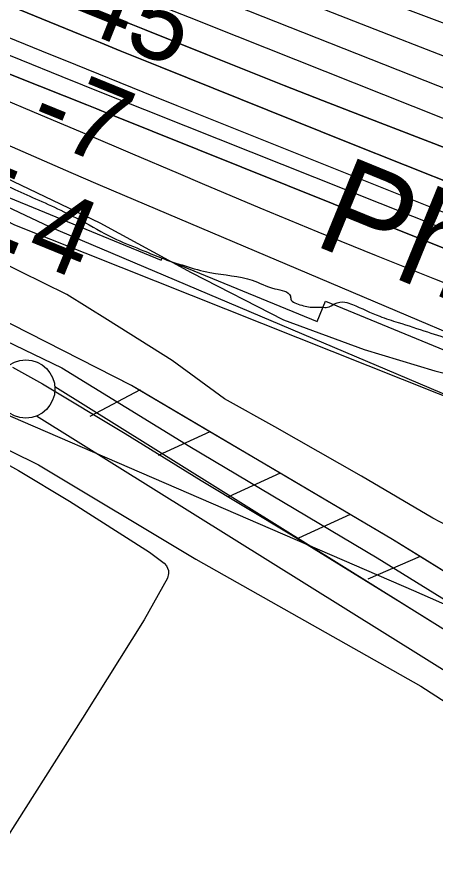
# Model space of a CAD drawing. Extents: x 3734862 to 3772949, y 391520 to 417239.
# Drawn here: x 3741807 to 3742167, y 404825 to 405557 of the extents above; entities that cross this region are included whole.
import ezdxf

# ---------------------------------------------------------------- set-up
doc = ezdxf.new("R2010")
doc.units = 0
for name, color, linetype in [('V-FLOD-BASE', 7, 'Continuous'), ('V-LEVE-TOET', 7, 'Continuous'), ('V-RIVR-EDGE', 7, 'Continuous'), ('V-RIVR-IDEN', 7, 'Continuous'), ('V-RIVR-RANG', 7, 'Continuous'), ('V-RRAP-FSHR', 7, 'Continuous'), ('V-RRAP-RVMT', 7, 'Continuous'), ('V-SITE-VEGE', 7, 'Continuous'), ('V-SURV-LINE', 7, 'Continuous'), ('V-TOPO-DPTH', 7, 'Continuous'), ('V-TOPO-MAJR', 7, 'Continuous'), ('V-TOPO-MINR', 7, 'Continuous'), ('V-TOPO-WATR', 7, 'Continuous')]:
    doc.layers.add(name, color=color, linetype=linetype)

msp = doc.modelspace()

# ---------------------------------------------------------------- linework, layer by layer
at = {"layer": 'V-FLOD-BASE'}
msp.add_lwpolyline([(3741803.04, 405256.38), (3741828.8, 405242.04), (3741899.63, 405199.43), (3741965.13, 405159.14), (3742042.8, 405112.37), (3742137.91, 405053.54), (3742242.67, 404988.23), (3742340.8, 404923.82), (3742458.41, 404848.76), (3742555.3, 404788.55), (3742592.78, 404766.32), (3742612.91, 404757.09), (3742638.17, 404748.81), (3742691.39, 404733.67), (3742795.22, 404705.71), (3742952.8, 404667.76), (3743127.33, 404622.89), (3743342.82, 404567.02), (3743492.56, 404528.55), (3743646.04, 404489.18), (3743813.84, 404444.74), (3743963.11, 404406.74), (3744124.34, 404367.87)], dxfattribs=at)
at = {"layer": 'V-LEVE-TOET'}
for points in [[(3741628.66, 405352.2), (3741780.31, 405287.13), (3741845.39, 405255.7), (3741955.4, 405188.08), (3742116.45, 405092.7), (3742264.88, 405000.53), (3742443.4, 404886.08), (3742584.27, 404792.47), (3742604.42, 404780.43), (3742616.12, 404773.95), (3742646.52, 404765.23), (3742696.1, 404751.48), (3742794.69, 404725.36), (3742931.43, 404690.1), (3743095.85, 404647.05), (3743222.3, 404615.94), (3743373.07, 404576.55), (3743548.44, 404530.75), (3743737.37, 404483.15), (3743928.07, 404434.62), (3744115.49, 404387.95)], [(3741753.52, 405207.65), (3741825.16, 405172.52), (3741960.54, 405091.48), (3742153.99, 404982.26), (3742330.64, 404868.28), (3742484.33, 404770.62), (3742534.1, 404736.31), (3742572.06, 404711.76), (3742601.56, 404696.49), (3742623.56, 404687.73), (3742687.16, 404671.25), (3742769.46, 404650.19), (3742877.96, 404621.79), (3743022.92, 404587.04), (3743222.97, 404536.69), (3743395.89, 404494.61), (3743549.66, 404453.84), (3743726.06, 404407.11), (3743908.05, 404364.14), (3744074.45, 404319.69), (3744212.77, 404285.38)]]:
    msp.add_lwpolyline(points, dxfattribs=at)
at = {"layer": 'V-RIVR-EDGE'}
msp.add_spline([(3740284.23, 406091.5), (3740310.88, 406078.89), (3740348.85, 406061.82), (3740353.7, 406060.59), (3740364.62, 406059.35), (3740372.7, 406056.5), (3740387.63, 406044.33), (3740395.71, 406041.89), (3740409.04, 406036.6), (3740430.04, 406026.44), (3740442.56, 406019.13), (3740451.45, 406015.46), (3740466, 406012.6), (3740476.5, 406010.15), (3740489.43, 406005.67), (3740507.61, 405997.13), (3740522.95, 405989), (3740544.36, 405977.63), (3740556.47, 405971.53), (3740569.81, 405967.86), (3740577.49, 405966.22), (3740592.04, 405964.57), (3740596.89, 405964.56), (3740607.4, 405960.08), (3740616.68, 405953.19), (3740635.67, 405946.27), (3740666.77, 405930.82), (3740697.87, 405917.81), (3740711.61, 405913.73), (3740727.77, 405908.03), (3740737.46, 405903.96), (3740772.6, 405884.87), (3740794.41, 405876.73), (3740819.46, 405866.96), (3740836.42, 405858.83), (3740859.04, 405847.05), (3740882.05, 405833.24), (3740901.84, 405822.28), (3740929.3, 405808.05), (3740946.26, 405798.31), (3740968.88, 405787.33), (3740998.36, 405770.68), (3741025.41, 405754.04), (3741050.85, 405741.44), (3741073.47, 405730.06), (3741090.84, 405721.93), (3741112.25, 405712.98), (3741151.03, 405698.33), (3741164.76, 405692.23), (3741182.94, 405682.88), (3741205.16, 405675.14), (3741229.4, 405665.78), (3741250.81, 405658.45), (3741277.48, 405649.89), (3741303.74, 405640.12), (3741333.23, 405627.52), (3741357.46, 405614.92), (3741386.54, 405602.72), (3741400.29, 405601.07), (3741418.87, 405593.74), (3741447.55, 405583.56), (3741468.56, 405576.63), (3741486.74, 405569.72), (3741500.88, 405562.4), (3741512.59, 405556.71), (3741522.69, 405552.64), (3741537.24, 405548.56), (3741581.27, 405532.28), (3741608.74, 405519.68), (3741642.25, 405499.78), (3741662.84, 405486.79), (3741679, 405477.85), (3741697.17, 405467.7), (3741715.33, 405455.12), (3741729.87, 405447.8), (3741754.11, 405435.61), (3741802.57, 405410.02), (3741822.76, 405401.07), (3741865.57, 405380.34), (3741892.23, 405366.12), (3741915.66, 405356.36), (3741930.6, 405350.26), (3741951.21, 405343.33), (3741972.63, 405337.62), (3742009, 405331.06), (3742028.4, 405323.73), (3742041.72, 405317.23), (3742042.52, 405313.99), (3742046.97, 405311.15), (3742058.68, 405307.89), (3742068.79, 405307.86), (3742073.65, 405307.85), (3742079.72, 405310.67), (3742088.62, 405312.26), (3742095.08, 405310.22), (3742118.51, 405300.06), (3742134.27, 405294.76), (3742159.72, 405286.61), (3742182.35, 405279.28), (3742201.34, 405273.97), (3742222.36, 405268.26), (3742239.73, 405262.15), (3742263.56, 405253.19), (3742278.91, 405245.07), (3742307.99, 405229.63), (3742326.16, 405219.48), (3742346.35, 405209.72), (3742373.82, 405199.55), (3742400.89, 405188.16), (3742413.41, 405180.44), (3742429.96, 405170.29), (3742436, 405161.79), (3742439.22, 405154.9), (3742444.47, 405149.63), (3742450.53, 405147.6), (3742468.31, 405143.91), (3742478.41, 405141.06), (3742497.4, 405134.14), (3742510.32, 405128.04), (3742527.69, 405119.91), (3742545.06, 405110.97), (3742567.68, 405100.4), (3742590.7, 405089.83), (3742639.16, 405063.83), (3742649.27, 405062.19), (3742658.97, 405062.16), (3742667.46, 405062.55), (3742676.76, 405060.5), (3742690.9, 405056.02), (3742714.33, 405045.85), (3742740.98, 405032.04), (3742759.96, 405022.29), (3742790.25, 405004.82), (3742814.09, 404997.08), (3742826.61, 404993.01), (3742844.39, 404988.11), (3742862.98, 404984.02), (3742878.74, 404979.94), (3742899.75, 404972.2), (3742910.66, 404970.15), (3742935.31, 404961.6), (3742961.17, 404953.85), (3742978.54, 404947.34), (3742993.89, 404940.02), (3743010.45, 404933.92), (3743026.22, 404931.45), (3743054.51, 404925.72), (3743082.4, 404921.61), (3743104.23, 404917.51), (3743119.99, 404913.83), (3743140.19, 404908.12), (3743171.31, 404899.96), (3743202.02, 404891.79), (3743227.88, 404884.05), (3743293.35, 404868.11)], degree=3, dxfattribs=at)
at = {"layer": 'V-RRAP-FSHR'}
for p, q in [((3741912.58, 405236.8), (3741869.48, 405213.85)), ((3741972.64, 405200.81), (3741928.19, 405180.58)), ((3742032.93, 405165.26), (3741988.49, 405145.02)), ((3742093.23, 405129.7), (3742048.79, 405109.47)), ((3742153.22, 405093.64), (3742108.35, 405074.36))]:
    msp.add_line(p, q, dxfattribs=at)
for points in [[(3744483.72, 404317.65), (3744096.93, 404414.47), (3743639.22, 404531.05), (3743120.19, 404667.02), (3742731.15, 404762.46), (3742601.75, 404809.4), (3742448.92, 404910.66), (3742129.46, 405108.34), (3741905.32, 405240.49), (3741772.84, 405307.91), (3741598.83, 405383.05), (3741291.51, 405502.33), (3740610.83, 405791.5), (3740295.5, 405923.92), (3740004.84, 406039.79)], [(3741468.97, 405553.07), (3741804.64, 405378.58), (3742229.12, 405209.73), (3742676.7, 405023.86), (3743148.5, 404867.63), (3744116.18, 404602.33), (3744824.73, 404371.64), (3745133.83, 404289.74), (3745755.59, 404164.01)], [(3741972.64, 405200.81), (3741912.34, 405236.36), (3741905.32, 405240.49), (3741891.3, 405247.63)], [(3742032.93, 405165.26), (3741972.63, 405200.81)], [(3742153.22, 405093.64), (3742129.46, 405108.34), (3742093.23, 405129.7), (3742032.93, 405165.26)], [(3742212.75, 405056.8), (3742153.22, 405093.64)]]:
    msp.add_lwpolyline(points, dxfattribs=at)
at = {"layer": 'V-RRAP-RVMT'}
for p, q in [((3741784.54, 405408.4), (3741930.75, 405348.36)), ((3741930.75, 405348.36), (3741931.56, 405350.32)), ((3741931.56, 405350.32), (3742064.88, 405295.58)), ((3742064.88, 405295.58), (3742071.99, 405313.02)), ((3742071.99, 405313.02), (3742203.86, 405258.85))]:
    msp.add_line(p, q, dxfattribs=at)
at = {"layer": 'V-SITE-VEGE'}
for p, q in [((3741765.79, 405434.09), (3741877.89, 405380.45)), ((3741877.89, 405380.45), (3741956.53, 405337.73)), ((3741849.51, 405318.8), (3741774.66, 405355.43)), ((3741956.53, 405337.73), (3742035.77, 405297.01)), ((3741884.66, 405297.11), (3741849.51, 405318.8)), ((3741940.07, 405262.13), (3741884.66, 405297.11)), ((3742035.77, 405297.01), (3742105.22, 405271.48)), ((3742105.22, 405271.48), (3742165.85, 405253.31)), ((3741985.24, 405229.28), (3741940.07, 405262.13)), ((3742165.85, 405253.31), (3742201.02, 405244.25)), ((3742028.38, 405205), (3741985.24, 405229.28)), ((3742103, 405162.87), (3742028.38, 405205)), ((3741776.49, 405185.15), (3741808.09, 405167.71)), ((3741808.09, 405167.71), (3741852.02, 405141.33)), ((3742164.19, 405126.67), (3742103, 405162.87)), ((3741852.02, 405141.33), (3741920.59, 405097.48)), ((3742234.62, 405090.07), (3742164.19, 405126.67)), ((3741920.59, 405097.48), (3741933.32, 405088.14)), ((3741933.32, 405088.14), (3741935.38, 405085.69)), ((3741935.38, 405085.69), (3741937.04, 405081.61)), ((3741937.04, 405081.61), (3741937.05, 405079.15)), ((3741936.25, 405075.06), (3741915.97, 405039.35)), ((3741937.05, 405079.15), (3741936.25, 405075.06)), ((3741915.97, 405039.35), (3741863.21, 404954.77)), ((3741863.21, 404954.77), (3741706.09, 404708))]:
    msp.add_line(p, q, dxfattribs=at)
at = {"layer": 'V-SURV-LINE'}
for points in [[(3741839.31, 405239.76), (3742605.89, 404761.9)], [(3742590, 404736.45), (3741823.42, 405214.31)]]:
    msp.add_lwpolyline(points, dxfattribs=at)
msp.add_circle((3741814.4, 405237.61), 25, dxfattribs=at)
at = {"layer": 'V-TOPO-DPTH'}
for points in [[(3743361.03, 405005.12), (3743264.08, 405033.99), (3743167.44, 405063.88), (3743071, 405094.46), (3742792.58, 405184.37), (3742771.64, 405191.29), (3742750.77, 405198.39), (3742729.99, 405205.77), (3742709.28, 405213.33), (3742484.84, 405297.03), (3742386.12, 405334.26), (3742287.59, 405371.99), (3742189.35, 405410.46), (3742091.3, 405449.43), (3741929.98, 405514.23), (3741912.74, 405521.18), (3741895.5, 405528.15), (3741878.28, 405535.15), (3741861.07, 405542.17), (3741377.23, 405740.01)], [(3741377.23, 405740.01), (3741861.07, 405542.17), (3741878.28, 405535.15), (3741895.5, 405528.15), (3741912.74, 405521.18), (3741929.98, 405514.23), (3742091.3, 405449.43), (3742189.35, 405410.46), (3742287.59, 405371.99), (3742386.12, 405334.26), (3742484.84, 405297.03), (3742709.28, 405213.33), (3742729.99, 405205.77), (3742750.77, 405198.39), (3742771.64, 405191.29), (3742792.58, 405184.37), (3743071, 405094.46), (3743167.44, 405063.88), (3743264.08, 405033.99), (3743361.03, 405005.12)], [(3741363.16, 405717.5), (3741827.93, 405528.13), (3741856.94, 405516.34), (3741885.97, 405504.59), (3741915.03, 405492.89), (3741944.1, 405481.24), (3742432.63, 405285.91), (3742483.41, 405265.92), (3742534.33, 405246.28), (3742585.45, 405227.17), (3742636.7, 405208.43), (3742670.87, 405196.13), (3742705.21, 405184), (3742739.64, 405172.15), (3742774.21, 405160.71), (3742808.87, 405149.55), (3743464.89, 404942.66)], [(3741363.16, 405717.5), (3741827.93, 405528.13), (3741856.94, 405516.34), (3741885.97, 405504.59), (3741915.03, 405492.89), (3741944.1, 405481.24), (3742432.63, 405285.91), (3742483.41, 405265.92), (3742534.33, 405246.28), (3742585.45, 405227.17), (3742636.7, 405208.43), (3742670.87, 405196.13), (3742705.21, 405184), (3742739.64, 405172.15), (3742774.21, 405160.71), (3742808.87, 405149.55), (3743464.89, 404942.66)], [(3741411.34, 405617.14), (3741807.19, 405443.51), (3741830.17, 405433.47), (3741853.19, 405423.5), (3741876.24, 405413.61), (3741899.31, 405403.78), (3742430.07, 405178.87), (3742474.44, 405160.54), (3742519.01, 405142.74), (3742563.9, 405125.75), (3742608.99, 405109.29), (3742628.6, 405102.33), (3742664.14, 405090.04), (3742699.81, 405078.13), (3742735.66, 405066.8), (3742771.64, 405055.85), (3743259.3, 404911.76), (3743317.23, 404894.56), (3743375.12, 404877.24)], [(3743608.54, 404969.82), (3743163.59, 405092.85), (3743095.73, 405112.17), (3743028.08, 405132.16), (3742960.74, 405153.18), (3742893.61, 405174.88), (3742779.49, 405212.72), (3742769.6, 405216.08), (3742759.74, 405219.53), (3742749.93, 405223.12), (3742740.15, 405226.81), (3742102.5, 405472.6), (3742069.45, 405485.43), (3742036.43, 405498.35), (3742003.47, 405511.42), (3741970.56, 405524.59), (3741916.27, 405546.44), (3741910.52, 405548.76), (3741904.78, 405551.08), (3741899.03, 405553.4), (3741893.29, 405555.73), (3741793.51, 405596.2)], [(3743608.54, 404969.82), (3743163.59, 405092.85), (3743095.73, 405112.17), (3743028.08, 405132.16), (3742960.74, 405153.18), (3742893.61, 405174.88), (3742779.49, 405212.72), (3742769.6, 405216.08), (3742759.74, 405219.53), (3742749.93, 405223.12), (3742740.15, 405226.81), (3742102.5, 405472.6), (3742069.45, 405485.43), (3742036.43, 405498.35), (3742003.47, 405511.42), (3741970.56, 405524.59), (3741916.27, 405546.44), (3741910.52, 405548.76), (3741904.78, 405551.08), (3741899.03, 405553.4), (3741893.29, 405555.73), (3741793.51, 405596.2)], [(3743596.77, 404859.69), (3742916.13, 405074.9), (3742884.22, 405085.11), (3742852.37, 405095.48), (3742820.59, 405106.08), (3742788.86, 405116.83), (3742733.58, 405135.79), (3742729.54, 405137.21), (3742725.52, 405138.66), (3742721.52, 405140.18), (3742717.53, 405141.73), (3742484.8, 405234.36), (3742383.16, 405274.86), (3742281.54, 405315.42), (3742179.96, 405356.06), (3742078.4, 405396.76), (3741883.69, 405474.87), (3741879.5, 405476.55), (3741875.31, 405478.22), (3741871.12, 405479.9), (3741866.93, 405481.58), (3741806.92, 405505.55), (3741772.71, 405519.18)], [(3743596.77, 404859.69), (3742916.13, 405074.9), (3742884.22, 405085.11), (3742852.37, 405095.48), (3742820.59, 405106.08), (3742788.86, 405116.83), (3742733.58, 405135.79), (3742729.54, 405137.21), (3742725.52, 405138.66), (3742721.52, 405140.18), (3742717.53, 405141.73), (3742484.8, 405234.36), (3742383.16, 405274.86), (3742281.54, 405315.42), (3742179.96, 405356.06), (3742078.4, 405396.76), (3741883.69, 405474.87), (3741879.5, 405476.55), (3741875.31, 405478.22), (3741871.12, 405479.9), (3741866.93, 405481.58), (3741806.92, 405505.55), (3741772.71, 405519.18)]]:
    msp.add_lwpolyline(points, dxfattribs=at)
at = {"layer": 'V-TOPO-MAJR'}
msp.add_lwpolyline([(3741782.75, 405625.7), (3741826.43, 405608.26), (3741831.81, 405606.11), (3741872.82, 405589.78), (3741913.82, 405573.44), (3741954.83, 405557.11), (3741995.83, 405540.78), (3742397.73, 405380.77), (3742459.13, 405356.39), (3742520.55, 405332.07), (3742582.02, 405307.87), (3742643.51, 405283.73), (3742763.54, 405236.74)], dxfattribs=at)
at = {"layer": 'V-TOPO-MINR'}
for points in [[(3741117.9, 405937.86), (3741894.7, 405632.82), (3741913.32, 405625.51), (3741931.93, 405618.2), (3741950.54, 405610.89), (3741969.15, 405603.59), (3742125.97, 405542.03), (3742223.13, 405504.32), (3742320.49, 405467.11), (3742418.12, 405430.66), (3742515.95, 405394.7), (3742754.75, 405307.96), (3742773.18, 405301.41), (3742791.68, 405295.04), (3742810.26, 405288.93), (3742828.9, 405283), (3742992.21, 405232.3), (3743092.6, 405201.3), (3743193.05, 405170.53), (3743293.6, 405140.07), (3743394.22, 405109.84)], [(3740989.32, 405776.2), (3741834.44, 405377.15), (3742641.79, 405034.91), (3742658.74, 405027.95), (3742675.8, 405021.25), (3742692.99, 405014.93), (3742710.29, 405008.88), (3742978.31, 404918.51), (3743079.31, 404887.29), (3743181.16, 404859.54), (3743284.29, 404837), (3743388.27, 404817.93), (3743597.52, 404785.02), (3744377.85, 404534.14)], [(3741377.23, 405740.01), (3741861.07, 405542.17), (3741878.28, 405535.15), (3741895.5, 405528.15), (3741912.74, 405521.18), (3741929.98, 405514.23), (3742091.3, 405449.43), (3742189.35, 405410.46), (3742287.59, 405371.99), (3742386.12, 405334.26), (3742484.84, 405297.03), (3742709.28, 405213.33), (3742729.99, 405205.77), (3742750.77, 405198.39), (3742771.64, 405191.29), (3742792.58, 405184.37), (3743071, 405094.46), (3743167.44, 405063.88), (3743264.08, 405033.99), (3743361.03, 405005.12)], [(3741587.56, 405728.15), (3741862.86, 405619.25), (3741892.81, 405607.4), (3741922.76, 405595.55), (3741952.72, 405583.7), (3741982.67, 405571.85), (3742458.88, 405383.5), (3742511.92, 405362.88), (3742565.12, 405342.69), (3742618.56, 405323.13), (3742672.15, 405304), (3742713.7, 405289.44), (3742746.72, 405278.16), (3742779.86, 405267.23), (3742813.15, 405256.83), (3742846.56, 405246.77), (3743244.78, 405130.27), (3743318.14, 405108.75), (3743391.48, 405087.16)], [(3741363.16, 405717.5), (3741827.93, 405528.13), (3741856.94, 405516.34), (3741885.97, 405504.59), (3741915.03, 405492.89), (3741944.1, 405481.24), (3742432.63, 405285.91), (3742483.41, 405265.92), (3742534.33, 405246.28), (3742585.45, 405227.17), (3742636.7, 405208.43), (3742670.87, 405196.13), (3742705.21, 405184), (3742739.64, 405172.15), (3742774.21, 405160.71), (3742808.87, 405149.55), (3743464.89, 404942.66)], [(3741791.59, 405701.13), (3741927.36, 405646.92), (3741934.33, 405644.15), (3741941.3, 405641.38), (3741948.29, 405638.64), (3741955.27, 405635.9), (3742012.84, 405613.42), (3742048.64, 405599.53), (3742084.47, 405585.73), (3742120.36, 405572.07), (3742156.29, 405558.51), (3742786.72, 405322.02), (3742793.82, 405319.41), (3742800.94, 405316.86), (3742808.09, 405314.41), (3742815.26, 405312.02), (3742892.15, 405286.93), (3742937.83, 405272.2), (3742983.58, 405257.69), (3743029.44, 405243.51), (3743075.36, 405229.55), (3743627.85, 405063.71)], [(3741793.51, 405596.2), (3741893.29, 405555.73), (3741899.03, 405553.4), (3741904.78, 405551.08), (3741910.52, 405548.76), (3741916.27, 405546.44), (3741970.56, 405524.59), (3742003.47, 405511.42), (3742036.43, 405498.35), (3742069.45, 405485.43), (3742102.5, 405472.6), (3742740.15, 405226.81), (3742749.93, 405223.12), (3742759.74, 405219.53), (3742769.6, 405216.08), (3742779.49, 405212.72), (3742893.61, 405174.88), (3742960.74, 405153.18), (3743028.08, 405132.16), (3743095.73, 405112.17), (3743163.59, 405092.85), (3743608.54, 404969.82)], [(3741692.35, 405567.73), (3741809.95, 405520.32), (3741845.38, 405506.06), (3741880.82, 405491.84), (3741916.28, 405477.67), (3741951.75, 405463.53), (3742618.12, 405198.49), (3742637.12, 405191.06), (3742656.16, 405183.78), (3742675.29, 405176.71), (3742694.48, 405169.79), (3742713.74, 405163.08), (3742733.05, 405156.51), (3742752.42, 405150.14), (3742771.85, 405143.92), (3743202.02, 405008.69), (3743273.88, 404986.1), (3743345.75, 404963.52)], [(3741772.71, 405519.18), (3741806.92, 405505.55), (3741866.93, 405481.58), (3741871.12, 405479.9), (3741875.31, 405478.22), (3741879.5, 405476.55), (3741883.69, 405474.87), (3742078.4, 405396.76), (3742179.96, 405356.06), (3742281.54, 405315.42), (3742383.16, 405274.86), (3742484.8, 405234.36), (3742717.53, 405141.73), (3742721.52, 405140.18), (3742725.52, 405138.66), (3742729.54, 405137.21), (3742733.58, 405135.79), (3742788.86, 405116.83), (3742820.59, 405106.08), (3742852.37, 405095.48), (3742884.22, 405085.11), (3742916.13, 405074.9), (3743596.77, 404859.69)], [(3741787.53, 405489.65), (3741827.02, 405473.07), (3741866.5, 405456.43), (3741905.93, 405439.7), (3741945.34, 405422.91), (3741965.8, 405414.17), (3742015.5, 405393.19), (3742065.33, 405372.5), (3742115.34, 405352.25), (3742165.47, 405332.29), (3742685.11, 405128.07), (3742700.56, 405122.15), (3742716.07, 405116.4), (3742731.68, 405110.92), (3742747.36, 405105.61), (3742922.93, 405047.76), (3743026.53, 405013.93), (3743130.23, 404980.45), (3743234.11, 404947.51), (3743338.11, 404914.92)], [(3741760.42, 405231.63), (3742147.52, 405064.59), (3742224.36, 405030.64), (3742300.78, 404995.8), (3742376.59, 404959.63), (3742451.98, 404922.58), (3742579.8, 404858.38), (3742591.08, 404853.01), (3742602.48, 404847.96), (3742614.09, 404843.4), (3742625.83, 404839.16), (3743100.43, 404678.96)]]:
    msp.add_lwpolyline(points, dxfattribs=at)
at = {"layer": 'V-TOPO-WATR'}
msp.add_lwpolyline([(3741411.34, 405617.14), (3741807.19, 405443.51), (3741830.17, 405433.47), (3741853.19, 405423.5), (3741876.24, 405413.61), (3741899.31, 405403.78), (3742430.07, 405178.87), (3742474.44, 405160.54), (3742519.01, 405142.74), (3742563.9, 405125.75), (3742608.99, 405109.29), (3742628.6, 405102.33), (3742664.14, 405090.04), (3742699.81, 405078.13), (3742735.66, 405066.8), (3742771.64, 405055.85), (3743259.3, 404911.76), (3743317.23, 404894.56), (3743375.12, 404877.24)], dxfattribs=at)

# ---------------------------------------------------------------- texts
at = {"layer": 'V-RIVR-IDEN'}
msp.add_text(' Photos', height=83, rotation=337.77153, dxfattribs=at).set_placement((3742031.21, 405373.75))
at = {"layer": 'V-RIVR-RANG'}
for s, rotation, p in [('-45', 338.12172, (3741822.77, 405561.26)), ('-7', 337.83833, (3741813.61, 405457.44)), ('5.4', 337.83833, (3741742.65, 405378.36))]:
    msp.add_text(s, height=67, rotation=rotation, dxfattribs=at).set_placement(p)

doc.saveas('drawing.dxf')
